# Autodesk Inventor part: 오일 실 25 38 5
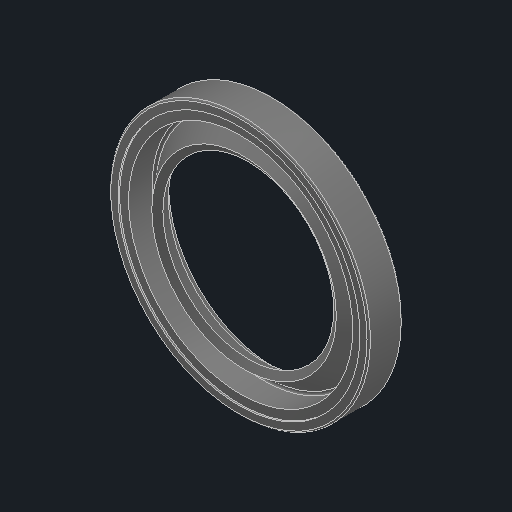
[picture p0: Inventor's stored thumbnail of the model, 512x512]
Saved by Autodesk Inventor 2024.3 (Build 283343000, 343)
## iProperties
Created: 2025-07
Part Number: 오일 실 25 38 5
Material: 고무
Description: 오일 실 - 비스프링, 조립 GA
Document SubType Name: Modeling
Designer: user
Density: 0.93 g/cm^3
Appearance: 기본값
Author: jhkim
Sending System: Autodesk Inventor 2026
Preprocessor: ST-DEVELOPER v20.1
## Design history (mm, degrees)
feature "Solid1"
node "솔리드1"
